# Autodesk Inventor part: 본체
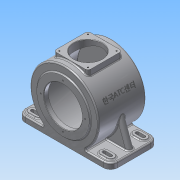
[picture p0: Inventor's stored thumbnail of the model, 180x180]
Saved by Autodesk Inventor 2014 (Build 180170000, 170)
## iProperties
Created: 2015-06
Part Number: 본체
Material: 알루미늄 6061
Document SubType Name: Modeling
Designer: Administrator
Density: 2.71 g/cm^3
Appearance: 알루미늄 - 평지
Mass: 3273.86 g
Surface Area: 2306.49 cm^2
Volume: 1208.06 cm^3
Author: Administrator
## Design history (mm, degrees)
sketch "스케치1"
  geometry: L1 (115, -59)-(-115, -59); L2 (-115, -59)-(-115, 59); L3 (-115, 59)-(115, 59); L4 (115, 59)-(115, -59); L5 (115, -59)-(-115, 59); L6 (-115, -59)-(115, 59); 1 further point
  constraints: 12 end point, 2 midpoint, 2 parallel, 1 horizontal, 1 perpendicular
  dimensions: "d0" = 230 distance of L2.end L3.end; "d1" = 118 distance of L1.end L2.end
extrude "돌출1" new body sketch "스케치1" distance "d2" = 14; taper "d3" = 0 deg
fillet "모깎기1" dims "d4" = 18
node "작업 평면1"
sketch "스케치2"
  geometry: L1 (194, 0)-(0, 0) reference; C1 r 65 at (97, 85); 1 further point
  constraints: 1 centre point, 1 vertical alignment
  dimensions: "d6" = 130 diameter of C1; "d7" = 85 distance from line of L1 C1.centre
extrude "돌출2" join sketch "스케치2" distance "d8" = 134; taper "d9" = 0 deg
sketch "스케치3"
  geometry: C1 r 65 at (97, 85) reference; C2 r 85 at (97, 85); 1 further point
  constraints: 1 centre point, 1 coincident
  dimensions: "d10" = 170 diameter of C2
extrude "돌출3" join sketch "스케치3" distance "d11" = 118; taper "d12" = 0 deg
node "작업 평면2"
sketch "스케치4"
  geometry: L1 (42.5, -42.5)-(-42.5, -42.5); L2 (-42.5, -42.5)-(-42.5, 42.5); L3 (-42.5, 42.5)-(42.5, 42.5); L4 (42.5, 42.5)-(42.5, -42.5); L5 (42.5, -42.5)-(-42.5, 42.5); L6 (-42.5, -42.5)-(42.5, 42.5); 1 further point
  constraints: 12 end point, 2 midpoint, 2 parallel, 2 perpendicular, 1 horizontal
  dimensions: "d14" = 85 distance of L2.end L3.end
extrude "돌출4" join sketch "스케치4" stored distance "d15" = 118; taper "d16" = 0 deg
hole "구멍1" diameter "d19" = 95; stored, may be unused: countersink angle "d23" = 90 deg, drill point angle "d25" = 0 deg; dims "d17" = 10, "d18" = 10, "d20" = 6, "d21" = 4, "d22" = 2, "d24" = 11
hole "구멍2" diameter "d28" = 154; stored, may be unused: countersink angle "d32" = 90 deg, drill point angle "d34" = 0 deg; dims "d29" = 6, "d30" = 154, "d31" = 102, "d33" = 102, "d113" = 10, "d114" = 10
sketch "스케치5"
  geometry: C1 r 35 at (0, 0); 1 further point
  constraints: 1 centre point, 1 coincident
  dimensions: "d44" = 70 diameter of C1
extrude "돌출5" cut sketch "스케치5" stored distance "d45" = 118; taper "d46" = 0 deg
sketch "스케치6"
  geometry: L1 (35.5, -35.5)-(-35.5, -35.5); L2 (-35.5, -35.5)-(-35.5, 35.5); L3 (-35.5, 35.5)-(35.5, 35.5); L4 (35.5, 35.5)-(35.5, -35.5); L5 (35.5, -35.5)-(-35.5, 35.5); L6 (-35.5, -35.5)-(35.5, 35.5); C1 r 35 at (0, 0) reference; 4 further points
  constraints: 12 end point, 4 coincident, 2 midpoint, 2 parallel, 2 perpendicular, 1 horizontal
  dimensions: "d47" = 71 distance of L2.end L3.end
hole "구멍4" sketch "스케치6" at (-35.5, 35.5), (-35.5, -35.5), (35.5, -35.5), (35.5, 35.5) diameter "d48" = 3.242; stored, may be unused: countersink angle "d52" = 90 deg, drill point angle "d54" = 118 deg; dims "d49" = 10, "d50" = 4, "d51" = 2, "d53" = 13
sketch "스케치7"
  geometry: C1 r 47.5 at (0, 0) reference; 2 further points
  constraints: 1 vertical alignment
  dimensions: "d55" = 55 distance of C1.centre point (0, 55)
hole "구멍5" sketch "스케치7" at (0, 55) diameter "d56" = 3.242; stored, may be unused: countersink angle "d60" = 90 deg, drill point angle "d62" = 118 deg; dims "d57" = 20, "d58" = 4, "d59" = 2, "d61" = 25
node "작업 평면3"
sketch "스케치8"
  geometry: L1 (0, 0)-(194, 0) reference; L2 (0, -14)-(0, 0) reference; L3 (50.267, -14)-(0, -14) reference; L4 (194, -14)-(143.733, -14) reference; L5 (194, 0)-(194, -14) reference; L6 (212, -14)-(194, -14) reference; L7 (0, -14)-(-18, -14) reference; L8 (-12, -14)-(12.13, -80.297); L9 (181.87, -80.297)-(206, -14); L10 (212, -14)-(212, 0) reference; L11 (-18, 0)-(-18, -14) reference; L12 (206, -14)-(143.733, -14); L13 (-12, -14)-(50.267, -14); C1 r 65 at (97, -85) reference; A1 r 85 centre (97, -85) between (50.267, -14) and (143.733, -14) reference; A2 r 85 centre (97, -85) between (181.87, -80.297) and (143.733, -14); A3 r 85 centre (97, -85) between (50.267, -14) and (12.13, -80.297); 1 further point
  constraints: 8 end point, 6 point on circle, 4 concentric, 2 centre point, 2 collinear, 2 point on line
  dimensions: "d68" = 110 deg angle of L7 L8; "d69" = 6 distance from line of L9.end L10; "d70" = 110 deg angle of L9 L6; "d71" = 6 distance from line of L11 L8.start
extrude "돌출6" join sketch "스케치8" stored distance "d72" = 15; taper "d73" = 0 deg
sketch "스케치9"
  geometry: L1 (-46.733, 59)-(-97, 59) reference; L2 (-97, 50)-(-81, 50); L3 (-81, 32)-(-97, 32); L4 (-97, -32)-(-81, -32); L5 (-81, -50)-(-97, -50); L6 (81, 50)-(97, 50); L7 (97, 32)-(81, 32); L8 (81, -32)-(97, -32); L9 (97, -50)-(81, -50); A1 r 18 centre (-97, 41) between (-97, 59) and (-115, 41) reference; A2 r 18 centre (-97, -41) between (-115, -41) and (-97, -59) reference; A3 r 9 centre (-81, 41) between (-81, 32) and (-81, 50); A4 r 9 centre (-97, 41) between (-97, 50) and (-97, 32); A5 r 9 centre (-97, -41) between (-97, -32) and (-97, -50); A6 r 9 centre (-81, -41) between (-81, -50) and (-81, -32); A7 r 9 centre (81, 41) between (81, 50) and (81, 32); A8 r 9 centre (97, 41) between (97, 32) and (97, 50); A9 r 9 centre (81, -41) between (81, -32) and (81, -50); A10 r 9 centre (97, -41) between (97, -50) and (97, -32); A11 r 18 centre (97, 41) between (115, 41) and (97, 59) reference; A12 r 18 centre (97, -41) between (97, -59) and (115, -41) reference; 1 further point
  constraints: 16 end point, 16 point on circle, 16 tangent, 8 centre point, 4 coincident, 4 horizontal alignment, 2 parallel
  dimensions: "d74" = 16 distance of L2.start L2.end; "d75" = 18 distance between parallel lines of L3 L2; "d77" = 16 distance of L4.start L4.end; "d78" = 18 distance between parallel lines of L5 L4; "d79" = 16 distance of L6.start L6.end; "d80" = 18 distance between parallel lines of L7 L6; "d81" = 16 distance of L8.start L8.end; "d82" = 18 distance between parallel lines of L9 L8
extrude "돌출7" join sketch "스케치9" distance "d83" = 3; taper "d84" = 0 deg
sketch "스케치10"
  geometry: L1 (-81, 50)-(-97, 50) reference; L2 (-97, 32)-(-81, 32) reference; L3 (-97, 45)-(-81, 45); L4 (-81, 37)-(-97, 37); L5 (-81, -32)-(-97, -32) reference; L6 (-97, -50)-(-81, -50) reference; L7 (97, 50)-(81, 50) reference; L8 (81, 32)-(97, 32) reference; L9 (97, -32)-(81, -32) reference; L10 (81, -50)-(97, -50) reference; L11 (-97, -37)-(-81, -37); L12 (-81, -45)-(-97, -45); L13 (81, -37)-(97, -37); L14 (97, -45)-(81, -45); L15 (81, 45)-(97, 45); L16 (97, 37)-(81, 37); A1 r 9 centre (-97, 41) between (-97, 50) and (-97, 32) reference; A2 r 9 centre (-81, 41) between (-81, 32) and (-81, 50) reference; A3 r 4 centre (-81, 41) between (-81, 37) and (-81, 45); A4 r 4 centre (-97, 41) between (-97, 45) and (-97, 37); A5 r 9 centre (-97, -41) between (-97, -32) and (-97, -50) reference; A6 r 9 centre (-81, -41) between (-81, -50) and (-81, -32) reference; A7 r 9 centre (81, 41) between (81, 50) and (81, 32) reference; A8 r 9 centre (97, 41) between (97, 32) and (97, 50) reference; A9 r 9 centre (81, -41) between (81, -32) and (81, -50) reference; A10 r 9 centre (97, -41) between (97, -50) and (97, -32) reference; A11 r 4 centre (-81, -41) between (-81, -45) and (-81, -37); A12 r 4 centre (-97, -41) between (-97, -37) and (-97, -45); A13 r 4 centre (97, -41) between (97, -45) and (97, -37); A14 r 4 centre (81, -41) between (81, -37) and (81, -45); A15 r 4 centre (97, 41) between (97, 37) and (97, 45); A16 r 4 centre (81, 41) between (81, 45) and (81, 37); 1 further point
  constraints: 16 end point, 16 point on circle, 8 centre point, 12 other
  dimensions: "d85" = 8 distance between parallel lines of L4 L3; "d86" = 8 distance between parallel lines of L12 L11; "d87" = 8 distance between parallel lines of L14 L13; "d88" = 8 distance between parallel lines of L16 L15
extrude "돌출8" cut sketch "스케치10" stored distance "d89" = 3; taper "d90" = 0 deg
sketch "스케치11"
  geometry: L1 (97, -85)-(19.964, -120.923); A1 r 85 centre (97, -85) between (50.267, -14) and (143.733, -14) reference; 3 further points
  constraints: 2 end point, 2 point on circle, 1 coincident, 1 horizontal alignment
  dimensions: "d91" = 25 deg dimension on L1.start L1.end point (12, -85)
node "작업 평면4"
sketch "스케치12"
  geometry: L1 (-62, 65)-(-62, -65) reference; L2 (-59, 65)-(-59, -65) reference; L3 (-59, -118.03)-(-59, -36.042) reference; L4 (-59, -105.342)-(-59, -118.03) reference; L5 (-59, -84.098)-(-59, -105.342) reference; L6 (-59, -84.098)-(-59, -44.598) reference; L7 (-59, -23.354)-(-59, -44.598) reference; L8 (-59, -36.042)-(-59, -23.354) reference; 4 further points
  constraints: 1 coincident, 1 other
  dimensions: "d92" = 59 distance from line of point (0, 0) L2; "d93" = 23.354 vertical distance of L7.start point (0, 0)
feature "엠보싱1" sketch "스케치12" dims "d94" = 0.5, "d95" = 0
fillet "모깎기2" dims "d96" = 0.3
fillet "모깎기4" dims "d98" = 3
fillet "모깎기6" dims "d100" = 7
fillet "모깎기9" dims "d103" = 3
fillet "모깎기20" dims "d135" = 7.5
fillet "모깎기21" dims "d136" = 3
fillet "모깎기18" dims "d133" = 3
fillet "모깎기14" dims "d108" = 3
fillet "모깎기15" dims "d109" = 3
chamfer "모따기1" distance "d110" = 1; stored, may be unused: second distance "d111" = 2, angle "d112" = 45 deg
sketch "스케치13"
  geometry: C1 r 76.7 at (0, 0) reference; C2 r 31 at (0, 0); 1 further point
  constraints: 1 centre point, 1 coincident
  dimensions: "d115" = 62 diameter of C2
extrude "돌출9" join sketch "스케치13" distance "d116" = 3.5; taper "d117" = -25 deg
hole "구멍6" diameter "d120" = 30; stored, may be unused: countersink angle "d124" = 90 deg, drill point angle "d126" = 0 deg; dims "d118" = 10, "d119" = 10, "d121" = 30, "d122" = 47, "d123" = 14, "d125" = 3
fillet "모깎기16" dims "d127" = 3, "d128" = 0.3
fillet "모깎기17" dims "d129" = 3
chamfer "모따기2" distance "d130" = 1; stored, may be unused: second distance "d131" = 2, angle "d132" = 45 deg
fillet "모깎기22" dims "d137" = 3
fillet "모깎기23" dims "d138" = 3
node "솔리드1"
pattern_circular "원형 패턴1" dims angle "d64" = 360 deg
node "투영된 루프1"
node "투영된 루프2"
node "투영된 루프3"
node "투영된 루프4"
node "투영된 루프5"
other parameters: "d5" = 13, "d13" = -173, "d66" = -59
